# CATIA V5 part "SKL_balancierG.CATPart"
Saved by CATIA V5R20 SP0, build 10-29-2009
Part number: SKL_balancierG
Publications: "Plan_Ref", "G", "Axe_G_balancierG", "E", "Segment_GE", "Axe_E_balancierG", "Plan_Sec", "Plan_Ter"
Bounding box of the stored display mesh (mm): x -5 to 5, y 0 to 2.632, z 0 to 5.79
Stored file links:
  C:\Users\MATT\Desktop\CATIA_Projet_IAO\CATIA FINAL\SKL_balancierG.CATPart
  C:\Users\MATT\Desktop\CATIA_Projet_IAO\CATIA FINAL\SKL_Parametre_Projet_IAO.CATProduct
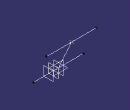
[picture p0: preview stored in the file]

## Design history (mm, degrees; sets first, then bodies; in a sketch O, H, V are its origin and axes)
External parameters (linked from other documents)
  External.AC = 3 mm
Set1
  Plane1 "Plan_Ref": type Offset, RefPlane Plane4, Offset 0
  Point1 "G": (0, 0, 0), relative to Point3
  Line1 "Axe_G_balancierG": type Normal, RefPoint Point1, RefSkin Plane1, Start -5, End 5
  Point2 "E": (0, 0, 0), relative to Point4
  Line2 "Segment_GE": type PtPt, FirstPoint Point1, SecondPoint Point2
  Line3 "Axe_E_balancierG": type Normal, RefPoint Point2, RefSkin Plane1, Start -5, End 5
  Plane2 "Plan_Sec": type Offset, RefPlane Plane5, Offset 0
  Plane3 "Plan_Ter": type Offset, RefPlane Plane6, Offset 0
Set2
  Plane4 "Plan_Ref": linked copy from another document
  Point3 "G": linked copy from another document
  Point4 "E": linked copy from another document
  Plane5 "Plan_Sec": linked copy from another document
  Plane6 "Plan_Ter": linked copy from another document
Body1 (main body)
